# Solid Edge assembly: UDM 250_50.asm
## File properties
Title: Zylinder
Author: ahadarics
Template: iso assembly.asm
Last saved by: ahadarics
Revision: 23
Application: Solid Edge
Username: ahadarics
Dokumentum tartalom típus: 1
Document Number: UDM 250/50
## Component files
Kit_1.par
Profilrohr 250_50.par
Zugstange 250_50.par
Kit_2.par
Mutter.par
Kolbenstange 250_50.par
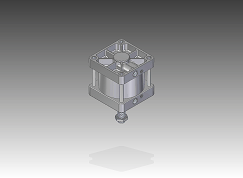
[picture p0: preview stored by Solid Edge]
